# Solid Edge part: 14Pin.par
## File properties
Author: conerly
Template: ansi part.par
Last saved by: alogan
Revision: 22
Application: Solid Edge
Density: 0.0979772159 lbm/in^3
Accuracy: 0.990
Material: Aluminum, 1060
Face Style: Aluminum
Fill Style: ANSI38(Aluminum)
Virtual Style: Polished aluminum
Coef. of Thermal Exp: 2.3e-05
Thermal Conductivity: 221.0
Specific Heat: 920.0
Modulus of Elasticity: 68947570000.0
Poisson's Ratio: 0.33
Yield Stress: 27579028.0
Ultimate Stress: 68947570.0
Elongation: 0.0
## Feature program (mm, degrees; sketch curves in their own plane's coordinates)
sketch for "unnamed Protrusion 1" plane through (10.8687, 0, 10.8687) normal (0, -1, 0) x-axis (1, 0, 0)
  line (-26.3687, -16.8687) -> (4.6313, -16.8687)
  line (4.6313, -16.8687) -> (4.6313, -4.8687)
  line (4.6313, -4.8687) -> (-26.3687, -4.8687)
  line (-26.3687, -4.8687) -> (-26.3687, -16.8687)
  dimension (linear) = 4.6313
  dimension (linear) = 26.3687
extrude "unnamed Protrusion 1" add finite 6.35 along -normal
sketch for "unnamed Cutout 1" plane through (0, 0, 0) normal (0, -1, 0) x-axis (1, 0, 0)
  circle centre (-12.96, 3.46) radius 1.27
extrude "unnamed Cutout 1" cut through along -normal
pattern "unnamed Pattern 1" of "unnamed Cutout 1"
extrude "unnamed Cutout 2" cut through
extrude "unnamed Cutout 3" cut through
extrude "unnamed Cutout 4" cut through
extrude "unnamed Cutout 5" cut through
extrude "unnamed Cutout 6" cut through
extrude "unnamed Cutout 7" cut through
extrude "unnamed Cutout 8" cut through
extrude "unnamed Cutout 9" cut through
extrude "unnamed Cutout 10" cut through
extrude "unnamed Cutout 11" cut through
extrude "unnamed Cutout 12" cut through
extrude "unnamed Cutout 13" cut through
extrude "unnamed Cutout 14" cut through
sketch for "ExtrudedProtrusion_2" plane through (0, 0, 0) normal (0, -1, 0) x-axis (1, 0, 0)
  line (-15.5, 1.5473) -> (15.5, 1.5473)
  line (15.5, 1.5473) -> (15.5, -1.0137)
  line (15.5, -1.0137) -> (-15.5, -1.0137)
  line (-15.5, -1.0137) -> (-15.5, 1.5473)
extrude "ExtrudedProtrusion_2" add finite 1.524 along +normal
sketch for "unnamed Protrusion 2" plane through (0, 0, -3.5069) normal (0, -1, 0) x-axis (1, 0, 0)
  line (-15.5, 9.5069) -> (-15.5, -2.4931)
  line (-15.5, -2.4931) -> (-14.4057, -2.4931)
  line (-14.4057, -2.4931) -> (-14.4057, 9.5069)
  line (-14.4057, 9.5069) -> (-15.5, 9.5069)
extrude "unnamed Protrusion 2" add to key point along +normal
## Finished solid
Body 1: solid body, 26 faces, 58 edges, 20 vertices.
  Faces by surface: cylinder 14, plane 12
  Edges by curve: line 30, circle 28
Bounding box of the edges (mm): 31.000 x 7.874 x 12.000, from (-15.5, -1.524, -6) to (15.5, 6.35, 6).
Cylindrical faces by radius (mm): R1.27 x14
Planar faces by outward normal: +x 3, +y 1, +z 2, -x 1, -y 3, -z 2
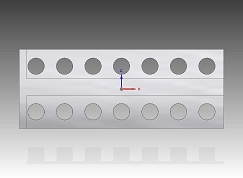
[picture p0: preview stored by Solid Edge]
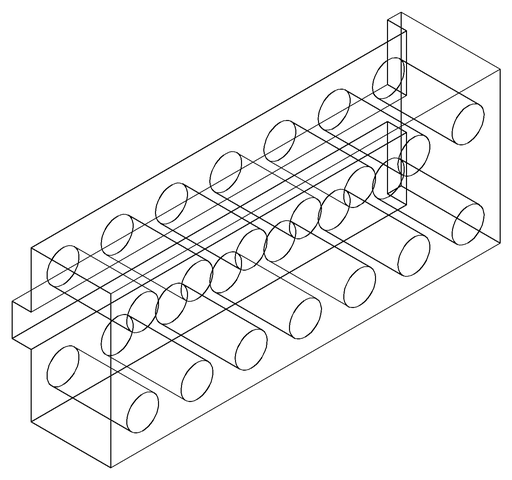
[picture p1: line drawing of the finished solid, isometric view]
